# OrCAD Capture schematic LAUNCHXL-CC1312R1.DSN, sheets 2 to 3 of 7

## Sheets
2 5_EnergyTrace: size A3
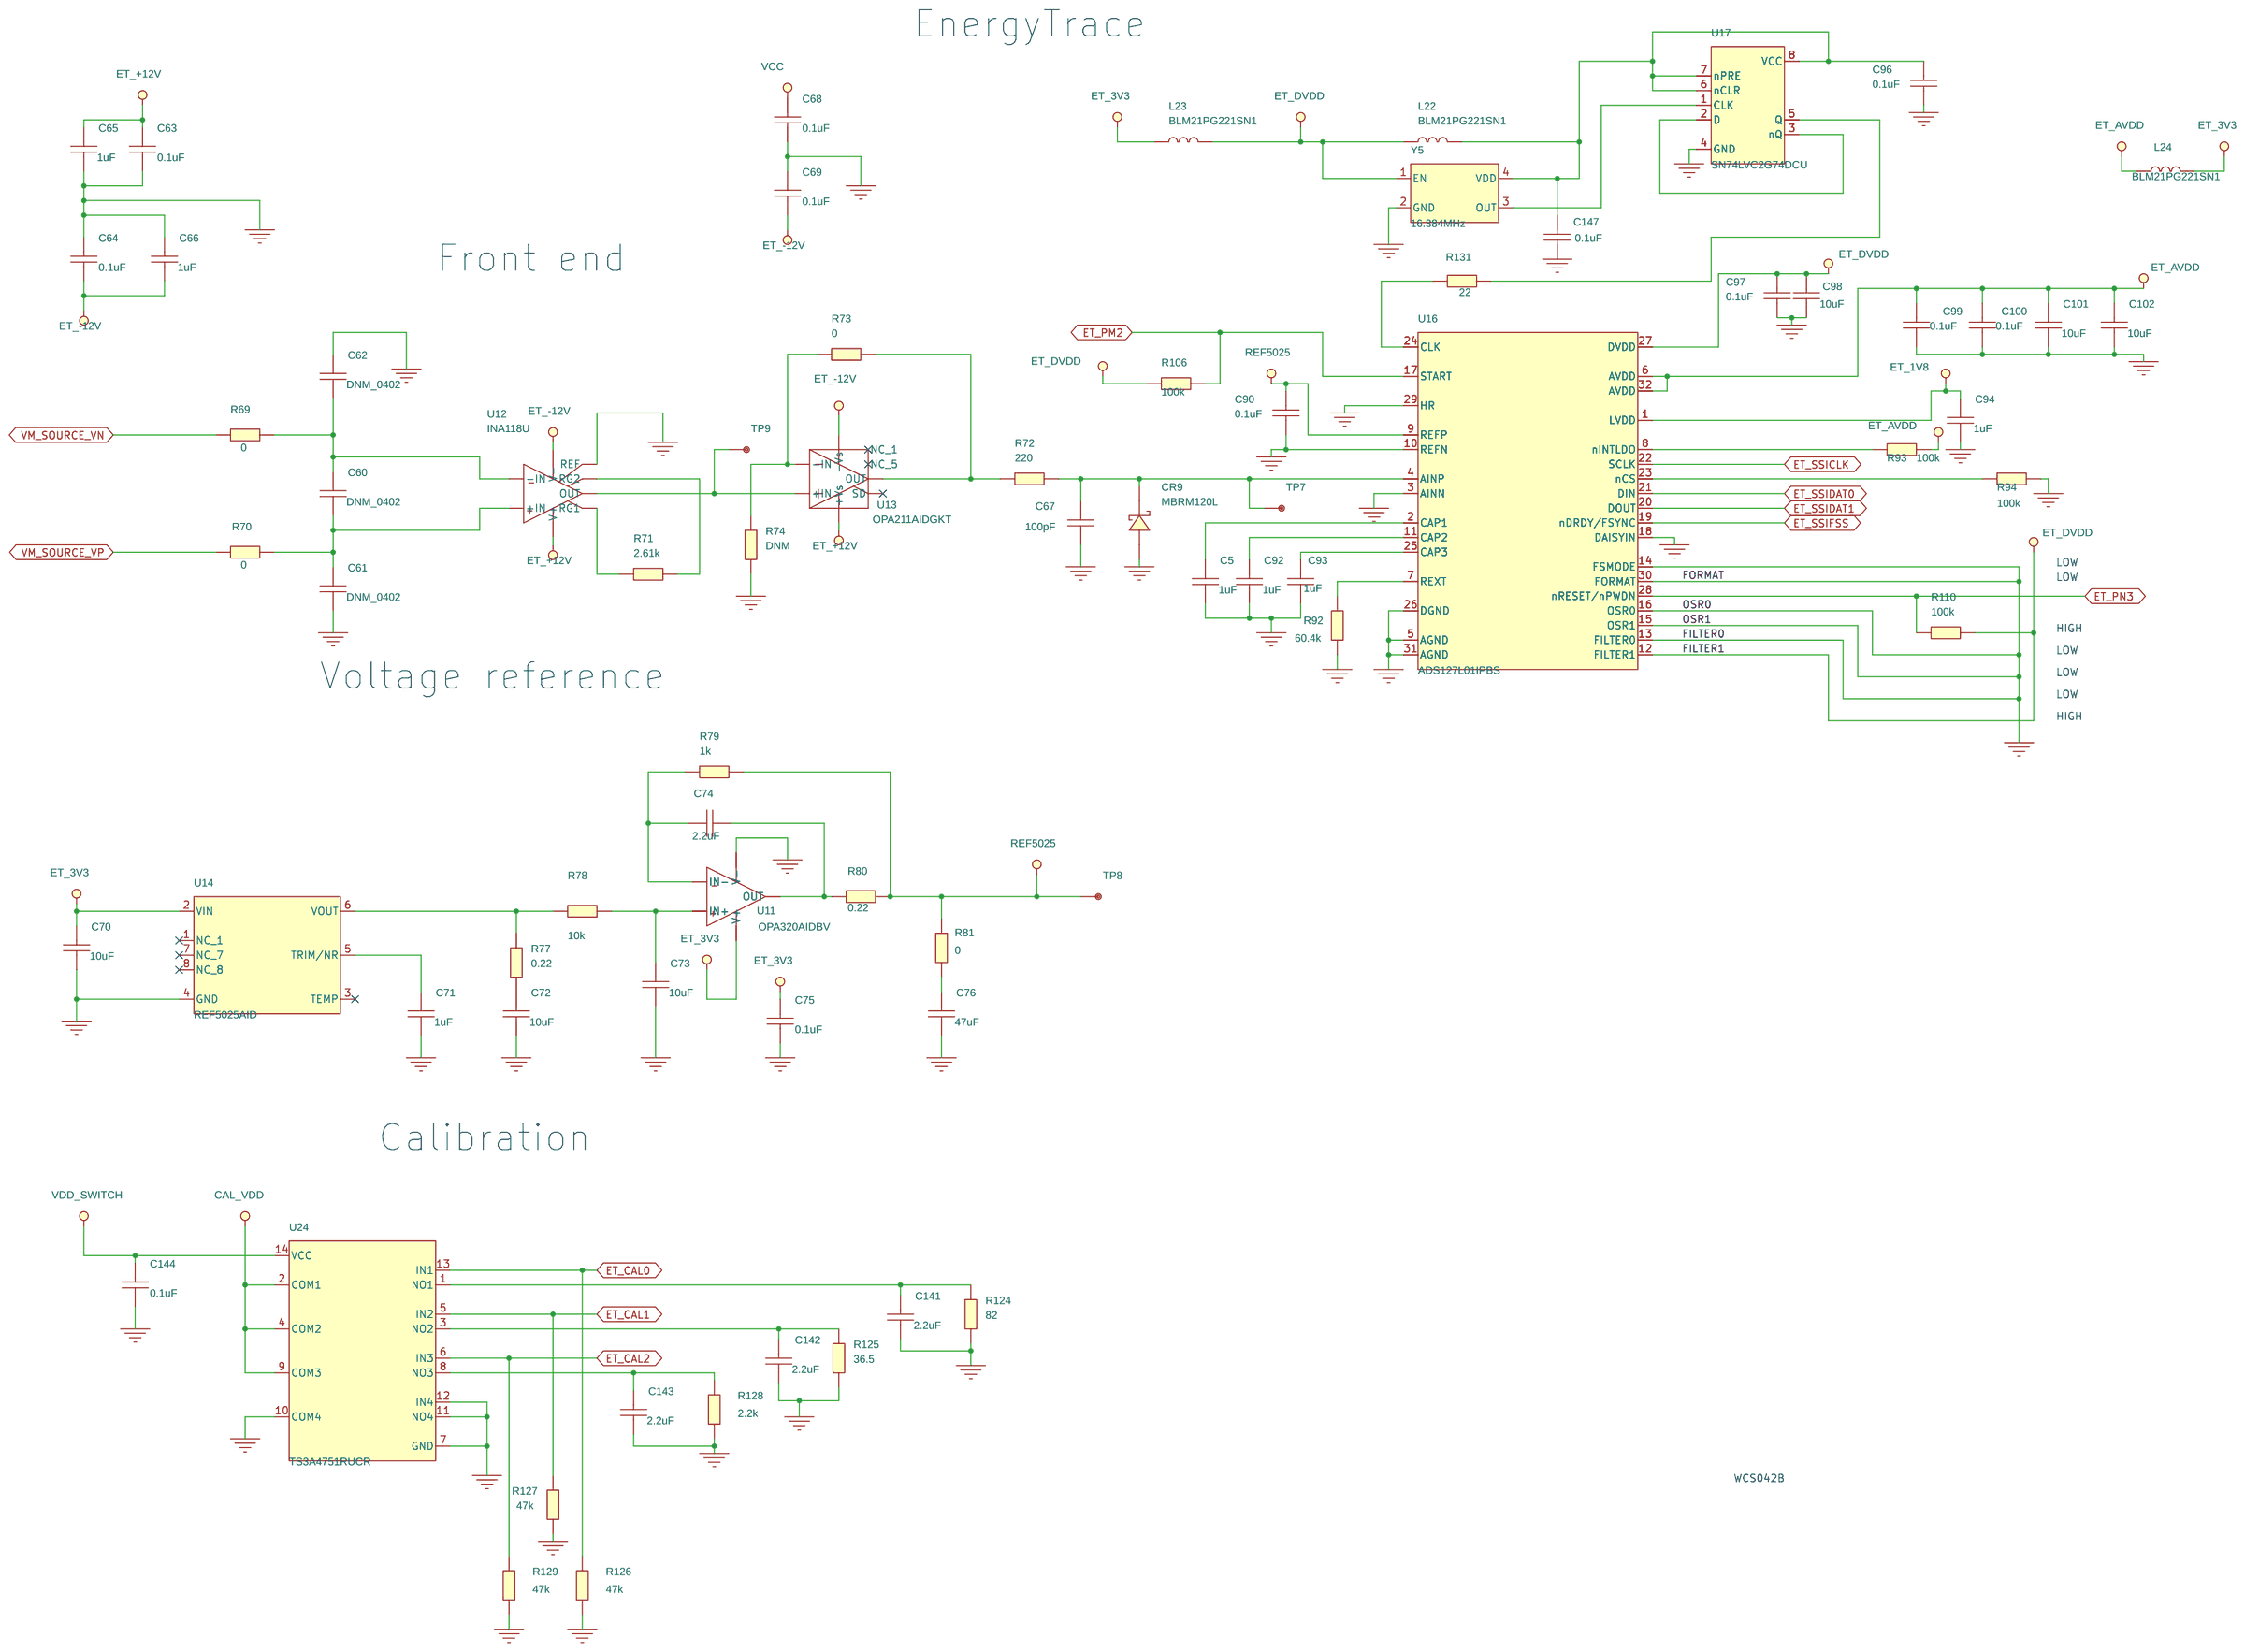
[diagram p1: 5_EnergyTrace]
3 7_Mech: size A3
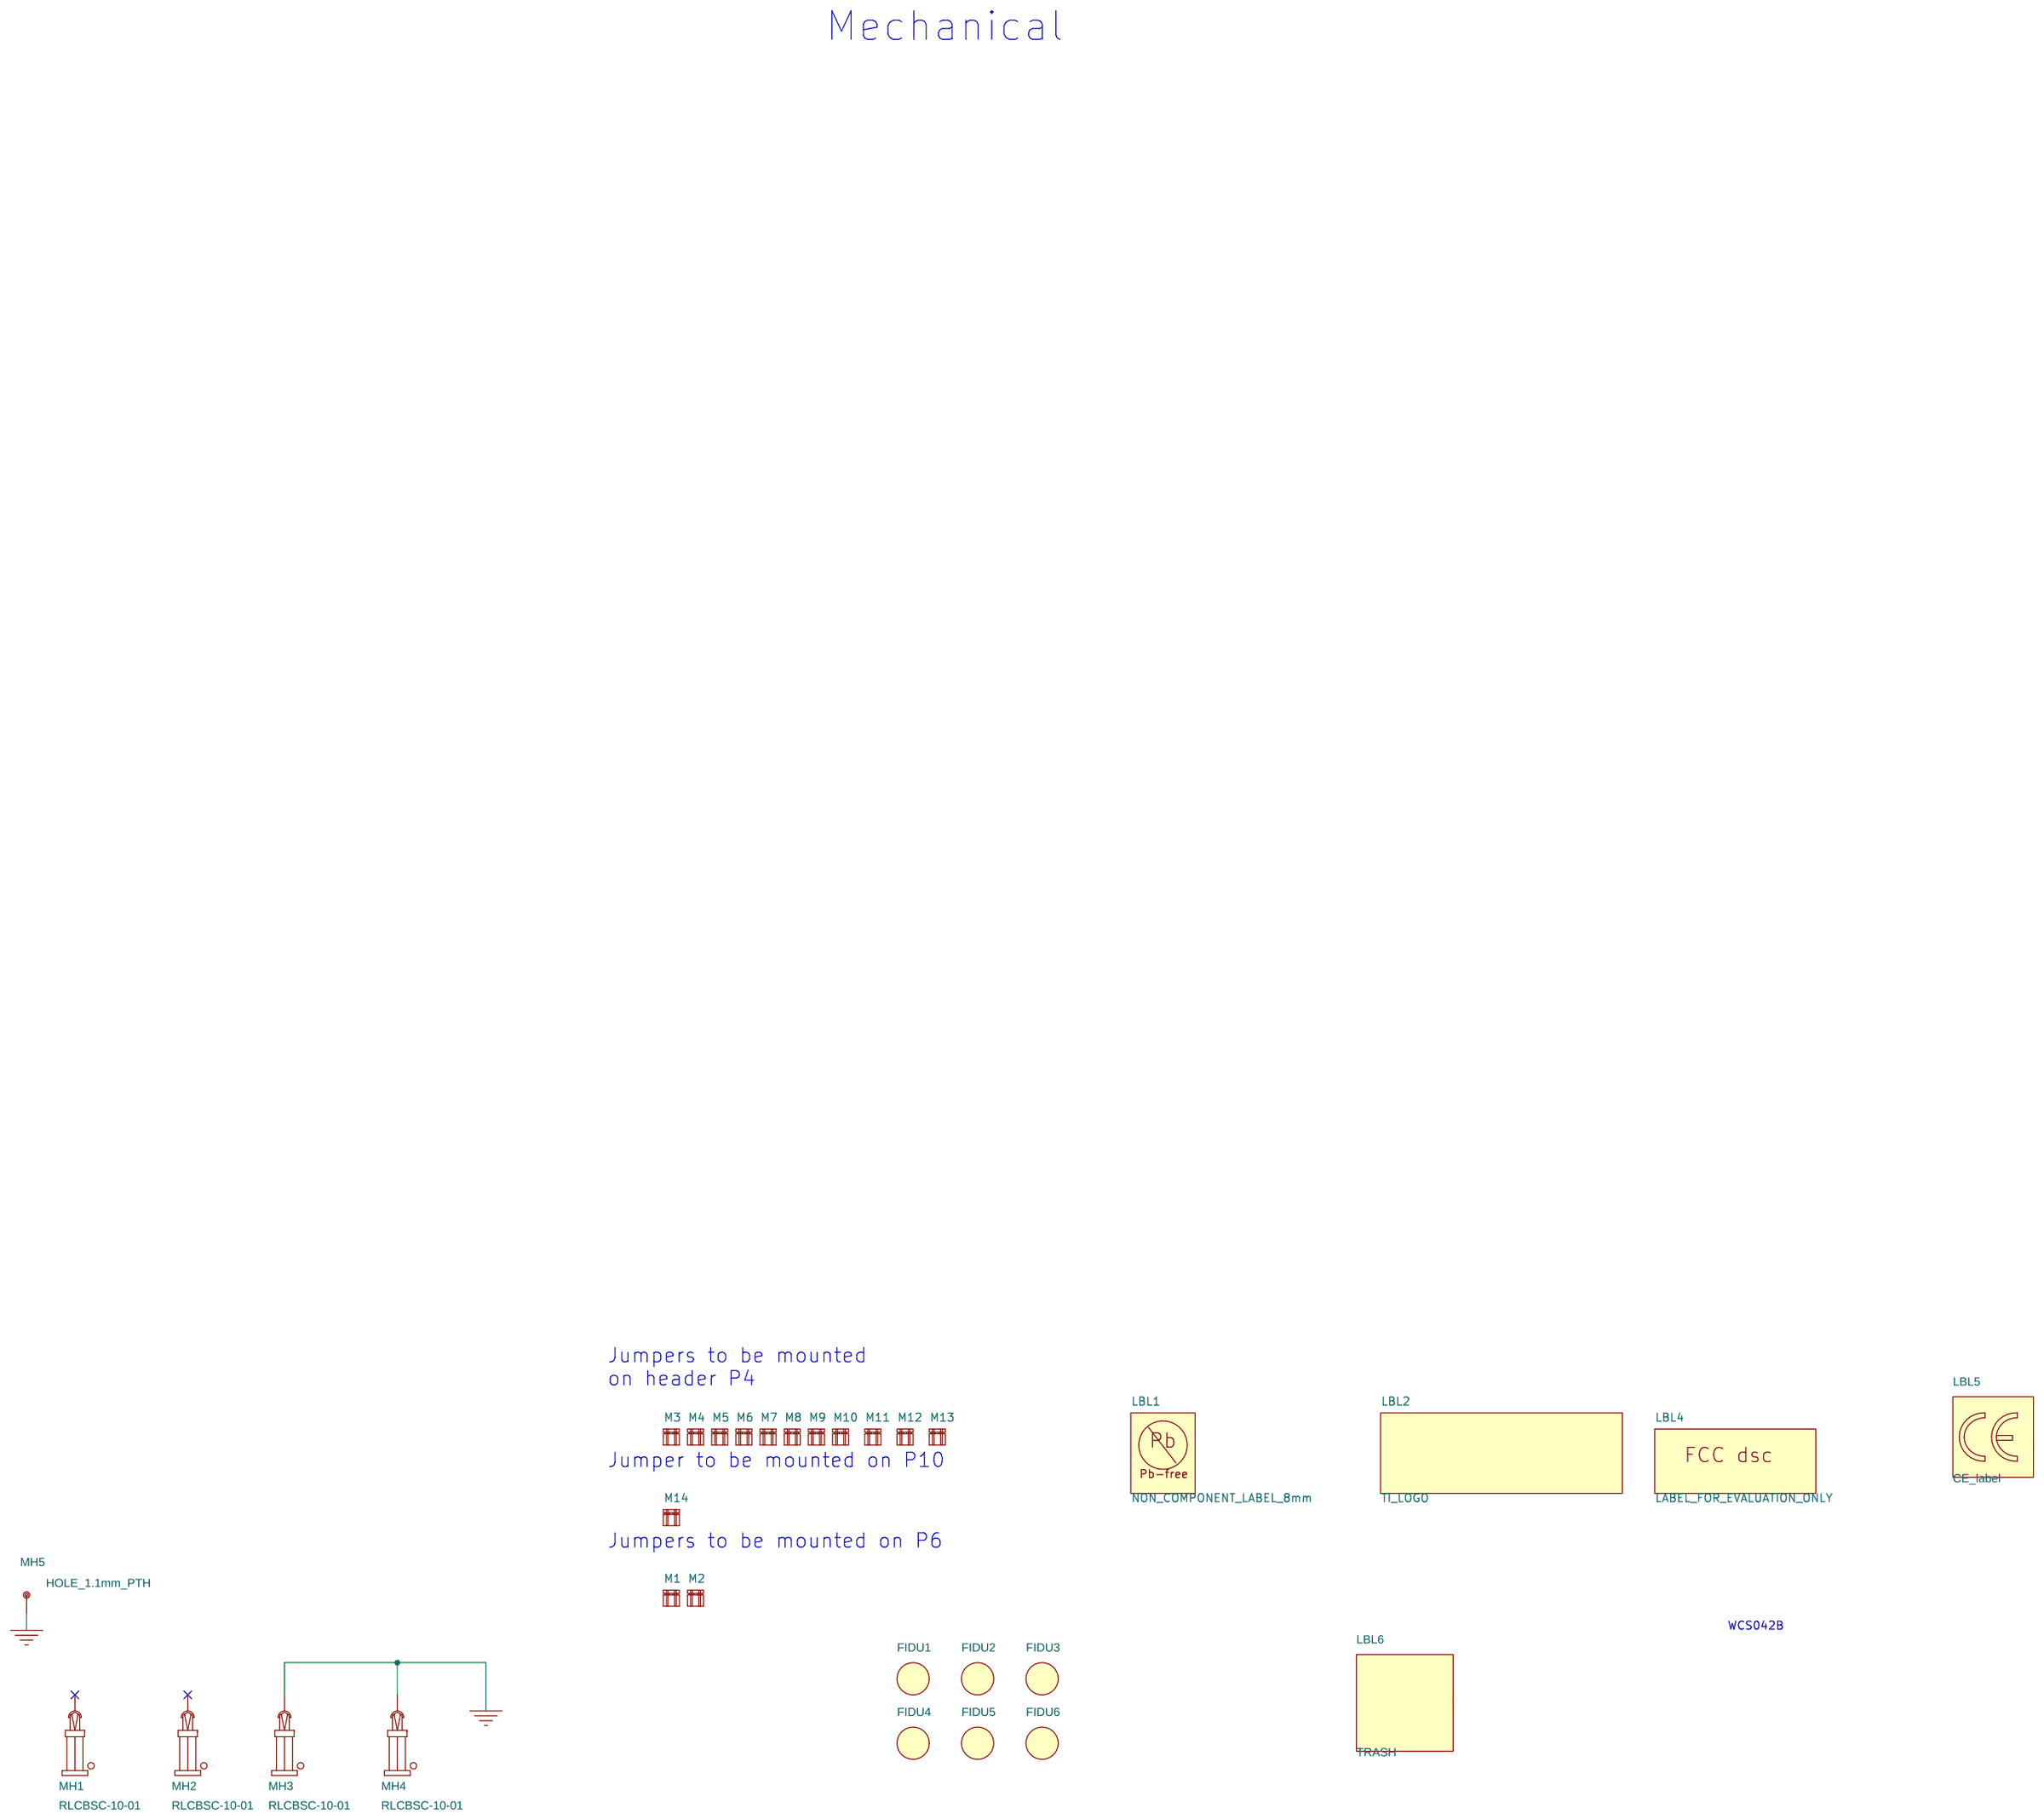
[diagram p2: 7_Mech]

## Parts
sheet 5_EnergyTrace
C5  1uF  [CAPC1005X60B2N]
C60  DNM_0402  [CAPC1005X60B2N]
C61  DNM_0402  [CAPC1005X60B2N]
C62  DNM_0402  [CAPC1005X60B2N]
C63  0.1uF  [CAPC1005X60B2N]
C64  0.1uF  [CAPC1005X60B2N]
C65  1uF  [CAPC1005X60B2N]
C66  1uF  [CAPC1005X60B2N]
C67  100pF  [CAPC1005X60B2N]
C68  0.1uF  [CAPC1005X60B2N]
C69  0.1uF  [CAPC1005X60B2N]
C70  10uF  [CAPC2012X150N]
C71  1uF  [CAPC1005X60B2N]
C72  10uF  [CAPC2012X150N]
C73  10uF  [CAPC2012X150N]
C74  2.2uF  [CAPC1005X60B2N]
C75  0.1uF  [CAPC1005X60B2N]
C76  47uF  [CAPC2012X150A2N]
C90  0.1uF  [CAPC1005X60B2N]
C92  1uF  [CAPC1005X60B2N]
C93  1uF  [CAPC1005X60B2N]
C94  1uF  [CAPC1005X60B2N]
C96  0.1uF  [CAPC1005X60B2N]
C97  0.1uF  [CAPC1005X60B2N]
C98  10uF  [CAPC2012X150N]
C99  0.1uF  [CAPC1005X60B2N]
C100  0.1uF  [CAPC1005X60B2N]
C101  10uF  [CAPC2012X150N]
C102  10uF  [CAPC2012X150N]
C141  2.2uF  [CAPC1005X60B2N]
C142  2.2uF  [CAPC1005X60B2N]
C143  2.2uF  [CAPC1005X60B2N]
C144  0.1uF  [CAPC1005X60B2N]
C147  0.1uF  [CAPC1005X60B2N]
CR9  MBRM120L  [DIO_MBRM120_A2N]
L22  BLM21PG221SN1  [INDC2012X150N]
L23  BLM21PG221SN1  [INDC2012X150N]
L24  BLM21PG221SN1  [INDC2012X150N]
R69  0  [RESC1005X40B2N]
R70  0  [RESC1005X40B2N]
R71  2.61k  [RESC1005X40N]
R72  220  [RESC1005X40B2N]
R73  0  [RESC1005X40B2N]
R74  DNM  [RESC1005X40B2N]
R77  0.22  [RESC1005X50A2N]
R78  10k  [RESC1005X40B2N]
R79  1k  [RESC1005X40A2N]
R80  0.22  [RESC1005X50A2N]
R81  0  [RESC1005X40B2N]
R92  60.4k  [RESC1005X40N]
R93  100k  [RESC1005X40B2N]
R94  100k  [RESC1005X40B2N]
R106  100k  [RESC1005X40B2N]
R110  100k  [RESC1005X40B2N]
R124  82  [RESC3216X75N]
R125  36.5  [RESC3225X75N]
R126  47k  [RESC1005X40N]
R127  47k  [RESC1005X40N]
R128  2.2k  [RESC1005X40A2N]
R129  47k  [RESC1005X40N]
R131  22  [RESC1005X40N]
TP7  HOLE_0.6mm_PTH  [MTG60_120]
TP8  HOLE_0.6mm_PTH  [MTG60_120]
TP9  HOLE_0.6mm_PTH  [MTG60_120]
U11  OPA320AIDBV  [SOT95P280X145-5A2N]
U12  INA118U  [SOIC127P600X175-8N]
U13  OPA211AIDGKT  [SOP65P490X110-8N]
U14  REF5025AID  [SOIC127P600X175-8A2N]
U16  ADS127L01IPBS  [QFP50P700X700X120-32A2N]
U17  SN74LVC2G74DCU  [SOP50P310X90-8N]
U24  TS3A4751RUCR  [QFNFC40P200X200X40-14A2N]
Y5  16.384MHz  [OSCSC508P500X700X180-4N]
sheet 7_Mech
FIDU1  FIDU_1.27mm  [FID127X142]
FIDU2  FIDU_1.27mm  [FID127X142]
FIDU3  FIDU_1.27mm  [FID127X142]
FIDU4  FIDU_1.27mm  [FID127X142]
FIDU5  FIDU_1.27mm  [FID127X142]
FIDU6  FIDU_1.27mm  [FID127X142]
LBL1  NON_COMPONENT_LABEL_8mm  [LABEL_PB-FREE_8MM_A2N]
LBL2  TI_LOGO  [TI_LOGO_1]
LBL4  LABEL_FOR_EVALUATION_ONLY  [LABEL_FOR_EVALUATION_ONLY]
LBL5  CE_label  [CE_label]
LBL6  TRASH  [TRASH]
M1  SNT-100-BK-G  [SAMTEC_SNT100BKG]
M2  SNT-100-BK-G  [SAMTEC_SNT100BKG]
M3  SNT-100-BK-G  [SAMTEC_SNT100BKG]
M4  SNT-100-BK-G  [SAMTEC_SNT100BKG]
M5  SNT-100-BK-G  [SAMTEC_SNT100BKG]
M6  SNT-100-BK-G  [SAMTEC_SNT100BKG]
M7  SNT-100-BK-G  [SAMTEC_SNT100BKG]
M8  SNT-100-BK-G  [SAMTEC_SNT100BKG]
M9  SNT-100-BK-G  [SAMTEC_SNT100BKG]
M10  SNT-100-BK-G  [SAMTEC_SNT100BKG]
M11  SNT-100-BK-G  [SAMTEC_SNT100BKG]
M12  SNT-100-BK-G  [SAMTEC_SNT100BKG]
M13  SNT-100-BK-G  [SAMTEC_SNT100BKG]
M14  SNT-100-BK-G  [SAMTEC_SNT100BKG]
MH1  RLCBSC-10-01  [MECH_RLCBSC1001_B2B]
MH2  RLCBSC-10-01  [MECH_RLCBSC1001_B2B]
MH3  RLCBSC-10-01  [MECH_RLCBSC1001_B2B]
MH4  RLCBSC-10-01  [MECH_RLCBSC1001_B2B]
MH5  HOLE_1.1mm_PTH  [MTG110_170]

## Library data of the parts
C5 C71 C92-C94 = CAPACITOR: CAPACITOR, CERAMIC X5R, 1uF, 16V, -10%/+10%, -55DEGC/+85DEGC, 0402, SMD; AutoDoc File: https://notefied-dynamic-precision.com/DB/Apps/Desktop/Item/Object.aspx?id=115295; BU Name: TEXAS INSTRUMENTS NORWAY; Client Status: UNDER_REVIEW; Datasheet URL 1: http://psearch.en.murata.com/capacitor/product/GRM155R61C105KA12%23.pdf; Datasheet URL 2: http://search.murata.co.jp/Ceramy/image/img/w_hinm/L0005E.pdf; Definied Quality: INDUSTRIAL; Dielectric Type: X5R; Esd Level: N/A; Last Time Buy: N/A; MPN: GRM155R61A105KE15D; MPN Status: ACTIVE; MSL: 1; MTBF: N/A; MTBF Standard: N/A; Manufacturer: MURATA; Max Oper Temp: +85DEGC; Max Tol: +10%; Min Oper Temp: -55DEGC; Min Tol: -10%; Mounting Type: SMD; NOTE Status: PREFERRED; Old Footprint: CAPC1005X60N,0402; PCB Package: 0402; Packing Size: 10000; Packing Type: TAPE_&_REEL; Part Number: 02-07863; Part Type: CAPACITOR\CERAMIC\0402\STANDARD; REACH/SVHC_COMPLIANCE: COMPLIANT; REACH/SVHC_DETAILS: SVHC LIST VERSION Jun 20, 2016; REACH/SVHC_SOURCE: REACH DECLARATION; REACH/SVHC_STATUS: UNAFFECTED; Revision: R002; RoHS Status: ROHS_COMPLIANT; Rtd Voltage: 16V; Vendor: MURATA; Vendor Part Number: GRM155R61C105KA12D; Vendor Part Status: ACTIVE; WEIGHT: 0.0016g
C60-C62 = CAPACITOR: CAPACITOR, CERAMIC, TBD, -55DEGC/+125DEGC, 0402, DNM, SMD; AutoDoc File: https://notefied-dynamic-precision.com/DB/Apps/Desktop/Item/Object.aspx?id=113344; BU Name: TEXAS INSTRUMENTS NORWAY; Budget Currency: USD; Budget Price: 0.00589; Country of Origin: MISSING INFO; Datasheet URL 1: N/A; Datasheet URL 2: N/A; Dielectric Type: MISSING-INFO; Last Time Buy: N/A; Lead Time: N/A; Max Oper Temp: +125DEGC; Min Oper Temp: -55DEGC; Mounting Type: SMD; PCB Package: 0402; Packing Size: 10000; Packing Type: TAPE_&_REEL; Part Number: 02-07616; Part Type: CAPACITOR\CERAMIC\0402\STANDARD; Revision: R000; RoHS Status: MISSING_INFO; Vendor: MANUFACTURER SELECTION; Vendor Part Number: CAPACITOR_0402_DNM_N/A_M; Vendor Part Status: ACTIVE; Weight: N/A
C63 C64 C68 C69 C75 C90 C96 C97 C99 C100 C144 C147 = CAPACITOR: CAPACITOR, CERAMIC X7R, 0.1uF, 25V, -10%/+10%, -55DEGC/+125DEGC, 0402, SMD; AutoDoc File: https://notefied-dynamic-precision.com/DB/Apps/Desktop/Item/Object.aspx?id=115293; BU Name: TEXAS INSTRUMENTS NORWAY; Client Status: UNDER_REVIEW; Datasheet URL 1: http://psearch.en.murata.com/capacitor/product/GRM155R71E104KE14%23.pdf; Datasheet URL 2: http://search.murata.co.jp/Ceramy/image/img/w_hinm/L0005E.pdf; Dielectric Type: X7R; Last Time Buy: N/A; LifeCycle Status: ACTIVE; MPN: GRM155R70J104KA01D; MPN Status: ACTIVE; Manufacturer: MURATA; Max Oper Temp: +125DEGC; Max Tol: +10%; Min Oper Temp: -55DEGC; Min Tol: -10%; Mounting Type: SMD; NOTE Status: PREFERRED; Old Footprint: CAPC1005X60N,0402; PCB Package: 0402; Packing Size: 10000; Packing Type: TAPE_&_REEL; Part Number: 02-07861; Part Type: CAPACITOR\CERAMIC\0402\STANDARD; REACH/SVHC_COMPLIANCE: COMPLIANT; REACH/SVHC_DETAILS: SVHC LIST VERSION Jun 20, 2016; REACH/SVHC_SOURCE: REACH DECLARATION; REACH/SVHC_STATUS: UNAFFECTED; Revision: R002; RoHS Status: ROHS_COMPLIANT; Rtd Voltage: 25V; Vendor: MURATA; Vendor Part Number: GRM155R71E104KE14D; Vendor Part Status: ACTIVE; WEIGHT: 0.0016g
C65 C66 = CAPACITOR: CAPACITOR, CERAMIC X5R, 1uF, 25V, -10%/+10%, -55DEGC/+85DEGC, 0402, SMD; AutoDoc File: https://notefied-dynamic-precision.com/DB/Apps/Desktop/Item/Object.aspx?id=115296; BU Name: TEXAS INSTRUMENTS NORWAY; Client Status: UNDER_REVIEW; Datasheet URL 1: http://psearch.en.murata.com/capacitor/product/GRM155R61E105KA12%23.pdf?graph=e32930247cd2da3b6fc5ccd8f3cf2bf2; Definied Quality: INDUSTRIAL; Dielectric Type: X5R; Esd Level: N/A; MPN: GRM155R61A105KE15D; MPN Status: ACTIVE; MSL: 1; MTBF: N/A; MTBF Standard: N/A; Manufacturer: MURATA; Max Oper Temp: +85DEGC; Max Tol: +10%; Min Oper Temp: -55DEGC; Min Tol: -10%; Mounting Type: SMD; NOTE Status: PREFERRED; Old Footprint: CAPC1005X60N,0402; PCB Package: 0402; Packing Size: 10000; Packing Type: TAPE_&_REEL; Part Number: 02-07864; Part Type: CAPACITOR\CERAMIC\0402\STANDARD; Revision: R001; RoHS Status: ROHS_COMPLIANT; Rtd Voltage: 25V; Vendor: MURATA; Vendor Part Number: GRM155R61E105KA12D; Vendor Part Status: ACTIVE; WEIGHT: 0.0016g
C67 = CAPACITOR: CAPACITOR, CERAMIC C0G/NP0, 100pF, 50V, -5%/+5%, -55DEGC/+125DEGC, 0402, SMD; AutoDoc File: https://notefied-dynamic-precision.com/DB/Apps/Desktop/Item/Object.aspx?id=113347; BU Name: TEXAS INSTRUMENTS NORWAY; Budget Currency: EUR; Budget Price: 0.004; Country of Origin: CHINA,PHILIPPINES; Datasheet URL 1: http://psearch.murata.com/capacitor/product/GRM1555C1H101JA01%23.pdf; Datasheet URL 2: http://search.murata.co.jp/Ceramy/image/img/w_hinm/L0005E.pdf; Dielectric Type: C0G/NP0; Last Time Buy: N/A; Lead Time: 12; Max Oper Temp: +125DEGC; Max Tol: +5%; Min Oper Temp: -55DEGC; Min Tol: -5%; Mounting Type: SMD; PCB Package: 0402; Packing Size: 10000; Packing Type: TAPE_&_REEL; Part Number: 02-07619; Part Type: CAPACITOR\CERAMIC\0402\STANDARD; REACH/SVHC_COMPLIANCE: COMPLIANT; REACH/SVHC_DETAILS: SVHC LIST VERSION Dec 17, 2015; REACH/SVHC_SOURCE: REACH DECLARATION; REACH/SVHC_STATUS: UNAFFECTED; Revision: R000; RoHS Status: ROHS_COMPLIANT; Rtd Voltage: 50V; Vendor: MURATA; Vendor Part Number: GRM1555C1H101JA01D; Vendor Part Status: ACTIVE; Weight: 0.0016g
C70 C72 C73 C98 C101 C102 = CAPACITOR: CAPACITOR, CERAMIC X7R, 10uF, 16V, -10%/+10%, -55DEGC/+125DEGC, 0805, SMD; ALT_SYMBOLS: CAPC2012X150L,CAPC2012X150M; AutoDoc File: https://notefied-dynamic-precision.com/DB/Apps/Desktop/Item/Object.aspx?id=94511; BU Name: DYNAMIC PRECISION GDANSK; Budget Currency: USD; Budget Price: 0.05; Client Status: UNDER_REVIEW; Country of Origin: SOUTH KOREA; Datasheet URL 1: http://www.samsungsem.com/kr/front/downloadcms.do?path=/kr/support/product-search/mlcc/__icsFiles/afieldfile/2015/10/15&fileName=S_CL21B106KOQNNNE.pdf; Datasheet URL 2: N/A; Dielectric Type: X7R; Last Time Buy: N/A; Lead Time: 11; Max Oper Temp: +125DEGC; Max Tol: +10%; Min Oper Temp: -55DEGC; Min Tol: -10%; Mounting Type: SMD; PCB Package: 0805; Packing Size: 2000; Packing Type: TAPE_&_REEL; Part Number: 02-05775; Part Type: CAPACITOR\CERAMIC\0805\STANDARD; Revision: R000; RoHS Status: ROHS_COMPLIANT; Rtd Voltage: 16V; Vendor: SAMSUNG ELECTRO-MECHANICS; Vendor Part Number: CL21B106KOQNNNE; Vendor Part Status: ACTIVE; Weight: 0.0166g
C74 C141-C143 = CAPACITOR: CAPACITOR, CERAMIC X5R, 2.2uF, 6.3V, -10%/+10%, -55DEGC/+85DEGC, 0402, SMD; AutoDoc File: https://notefied-dynamic-precision.com/DB/Apps/Desktop/Item/Object.aspx?id=113352; BU Name: TEXAS INSTRUMENTS NORWAY; Budget Currency: USD; Budget Price: 0.0126; Country of Origin: PHILIPPINES; Datasheet URL 1: http://psearch.murata.com/capacitor/product/GRM155R60J225KE95%23.pdf; Datasheet URL 2: http://psearch.en.murata.com/capacitor/product/GRM155R60J225KE95%23.html; Dielectric Type: X5R; Last Time Buy: N/A; Lead Time: N/A; Max Oper Temp: +85DEGC; Max Tol: +10%; Min Oper Temp: -55DEGC; Min Tol: -10%; Mounting Type: SMD; PCB Package: 0402; Packing Size: 10000; Packing Type: TAPE_&_REEL; Part Number: 02-07624; Part Type: CAPACITOR\CERAMIC\0402\STANDARD; Revision: R000; RoHS Status: ROHS_COMPLIANT; Rtd Voltage: 6.3V; Vendor: MURATA; Vendor Part Number: GRM155R60J225KE95D; Vendor Part Status: NRND; Weight: 0.0016g
C76 = CAPACITOR: CAPACITOR, CERAMIC X5R, 47uF, 10V, -20%/+20%, -55DEGC/+85DEGC, 0805, SMD; ALT_SYMBOLS: CAPC2012X150A2L,CAPC2012X150A2M; AutoDoc File: https://notefied-dynamic-precision.com/DB/Apps/Desktop/Item/Object.aspx?id=114133; BU Name: DYNAMIC PRECISION GDANSK; Client Status: UNDER_REVIEW; Datasheet URL 1: http://psearch.en.murata.com/capacitor/product/GRM21BR61A476ME15%23.pdf; Datasheet URL 2: N/A; Dielectric Type: X5R; Last Time Buy: N/A; Max Oper Temp: +85DEGC; Max Tol: +20%; Min Oper Temp: -55DEGC; Min Tol: -20%; Mounting Type: SMD; PCB Package: 0805; Packing Size: 3000; Packing Type: TAPE_&_REEL; Part Number: 02-07728; Part Type: CAPACITOR\CERAMIC\0805\STANDARD; Revision: R001; RoHS Status: ROHS_COMPLIANT; Rtd Voltage: 10V; Vendor: MURATA; Vendor Part Number: GRM21BR61A476ME15L; Vendor Part Status: ACTIVE; Weight: 0.023g
CR9 = DIODE_SCH_0: DIODE, SCHOTTKY POWER RECTIFIER, 20V, 1A, -55DEGC/+125DEGC, SMD; ALT_SYMBOLS: DIO_MBRM120_A2L,DIO_MBRM120_A2M; AutoDoc File: https://notefied-dynamic-precision.com/DB/Apps/Desktop/Item/Object.aspx?id=54665; BU Name: DYNAMIC PRECISION GDANSK; Budget Currency: USD; Budget Price: 0.12; Client Status: UNDER_REVIEW; Country of Origin: UNITED STATES; Datasheet URL 1: http://www.onsemi.com/pub/Collateral/MBRM120L-D.PDF; Datasheet URL 2: http://www.onsemi.com/pub/Collateral/457-04.PDF; Last Time Buy: N/A; Lead Time: 5; Max Oper Temp: +125DEGC; Min Oper Temp: -55DEGC; Mounting Type: SMD; Packing Size: 12000; Packing Type: TAPE_&_REEL; Part Number: 14-03151; Part Type: DIODE\SCHOTTKY; Revision: R002; RoHS Status: ROHS_COMPLIANT; Rtd Current: 1A; Rtd Voltage: 20V; Vendor: ON SEMICONDUCTOR; Vendor Part Number: MBRM120LT3G; Vendor Part Status: ACTIVE; Weight: 0.0163g
L22-L24 = INDUCTOR: FILTER, EMI, FERRITE BEAD, 220@100MHz, -25%/+25%, -55DEGC/+125DEGC, 0805, SMD; ALT_SYMBOLS: INDC2012X150L,INDC2012X150M; AutoDoc File: https://notefied-dynamic-precision.com/DB/Apps/Desktop/Item/Object.aspx?id=15278; BU Name: DYNAMIC PRECISION GDANSK; Budget Currency: EUR; Budget Price: 0.03; Client Status: UNDER_REVIEW; Country of Origin: JAPAN,SINGAPORE,THAILAND; Datasheet URL 1: http://search.murata.co.jp/Ceramy/image/img/PDF/ENG/L0110S0100BLM21P.pdf; Datasheet URL 2: http://search.murata.co.jp/Ceramy/image/img/w_hinm/L0110E.pdf; Frequency: 100MHz; Impedance: 220; Inductance: N/A; Last Time Buy: N/A; Lead Time: 9; Max Oper Temp: +125DEGC; Max Tol: +25%; Min Oper Temp: -55DEGC; Min Tol: -25%; Mounting Type: SMD; PCB Package: 0805; Packing Size: 4000; Packing Type: TAPE_&_REEL; Part Number: 04-00050; Part Type: FILTER\EMI\FERRITE_BEAD\0805; Resistance: 0.045; Revision: R002; RoHS Status: ROHS_COMPLIANT; Rtd Current: 2A; Rtd Voltage: N/A; Vendor: MURATA; Vendor Part Number: BLM21PG221SN1D; Vendor Part Status: ACTIVE; Weight: 0.0098g
R69 R70 R73 R81 = RESISTOR: RESISTOR, THICK FILM, 0, 0.063W, 50V, -55DEGC/+155DEGC, 0402, SMD; AutoDoc File: https://notefied-dynamic-precision.com/DB/Apps/Desktop/Item/Object.aspx?id=114568; BU Name: TEXAS INSTRUMENTS NORWAY; Budget Currency: EUR; Budget Price: 0.007; Client Status: UNDER_REVIEW; Country of Origin: ISRAEL; Datasheet URL 1: http://www.vishay.com/docs/20035/dcrcwe3.pdf; Datasheet URL 2: N/A; Last Time Buy: N/A; Lead Time: 14; Max Oper Temp: +155DEGC; Max TC: N/A; Max Tol: N/A; Min Oper Temp: -55DEGC; Min TC: N/A; Min Tol: N/A; Mounting Type: SMD; PCB Package: 0402; Packing Size: 10000; Packing Type: TAPE_&_REEL; Part Number: 01-22495; Part Type: RESISTOR\0402\JUMPER; REACH/SVHC_COMPLIANCE: COMPLIANT; REACH/SVHC_DETAILS: SVHC LIST VERSION Dec 17, 2015; REACH/SVHC_SOURCE: MATERIAL DECLARATION; REACH/SVHC_STATUS: UNAFFECTED; Resistor Type: THICK FILM; Revision: R000; RoHS Status: ROHS_COMPLIANT_WITH_EXEMPTION; Rtd Current: N/A; Rtd Power: 0.063W; Rtd Voltage: 50V; Vendor: VISHAY; Vendor Part Number: CRCW04020000Z0ED; Vendor Part Status: ACTIVE; Weight: 0.0006152g
R71 = RESISTOR: RESISTOR, THICK FILM, 2.61k, -1%/+1%, 0.063W, 50V, -55DEGC/+155DEGC, 0402, SMD; ALT_SYMBOLS: RESC1005X40L,RESC1005X40M; AutoDoc File: https://notefied-dynamic-precision.com/DB/Apps/Desktop/Item/Object.aspx?id=59349; BU Name: DYNAMIC PRECISION GDANSK; Budget Currency: EUR; Budget Price: 0.016; Country of Origin: ISRAEL; Datasheet URL 1: http://www.vishay.com/docs/20035/dcrcwe3.pdf; Datasheet URL 2: N/A; Last Time Buy: N/A; Lead Time: 18; Max Oper Temp: +155DEGC; Max TC: +100PPM/DEGC; Max Tol: +1%; Min Oper Temp: -55DEGC; Min TC: -100PPM/DEGC; Min Tol: -1%; Mounting Type: SMD; PCB Package: 0402; Packing Size: 10000; Packing Type: TAPE_&_REEL; Part Number: 01-04542; Part Type: RESISTOR\0402\PRECISION; Resistor Type: THICK FILM; Revision: R001; RoHS Status: ROHS_COMPLIANT; Rtd Current: N/A; Rtd Power: 0.063W; Rtd Voltage: 50V; Vendor: VISHAY; Vendor Part Number: CRCW04022K61FKED; Vendor Part Status: ACTIVE; Weight: 0.00065g
R72 = RESISTOR: RESISTOR, THICK FILM, 220, -5%/+5%, 0.063W, 50V, -55DEGC/+155DEGC, 0402, SMD; AutoDoc File: https://notefied-dynamic-precision.com/DB/Apps/Desktop/Item/Object.aspx?id=113319; BU Name: TEXAS INSTRUMENTS NORWAY; Budget Currency: EUR; Budget Price: 0.014; Client Status: UNDER_REVIEW; Country of Origin: ISRAEL; Datasheet URL 1: http://www.vishay.com/docs/20035/dcrcwe3.pdf; Datasheet URL 2: N/A; Last Time Buy: N/A; Lead Time: 18; Max Oper Temp: +155DEGC; Max TC: +200PPM/DEGC; Max Tol: +5%; Min Oper Temp: -55DEGC; Min TC: -200PPM/DEGC; Min Tol: -5%; Mounting Type: SMD; PCB Package: 0402; Packing Size: 10000; Packing Type: TAPE_&_REEL; Part Number: 01-22346; Part Type: RESISTOR\0402\STANDARD; REACH/SVHC_COMPLIANCE: COMPLIANT; REACH/SVHC_DETAILS: SVHC LIST VERSION Jun 20, 2016; REACH/SVHC_SOURCE: MATERIAL DECLARATION; REACH/SVHC_STATUS: UNAFFECTED; Resistor Type: THICK FILM; Revision: R001; RoHS Status: ROHS_COMPLIANT_WITH_EXEMPTION; Rtd Current: N/A; Rtd Power: 0.063W; Rtd Voltage: 50V; Vendor: VISHAY; Vendor Part Number: CRCW0402220RJNED; Vendor Part Status: ACTIVE; Weight: 0.00065g
R74 = RESISTOR: RESISTOR, DO NOT MOUNT, 0402, SMD; AutoDoc File: https://notefied-dynamic-precision.com/DB/Apps/Desktop/Item/Object.aspx?id=113312; BU Name: TEXAS INSTRUMENTS NORWAY; Budget Currency: N/A; Budget Price: N/A; Country of Origin: MISSING INFO; Datasheet URL 1: N/A; Datasheet URL 2: N/A; Last Time Buy: N/A; Lead Time: N/A; Max Oper Temp: N/A; Max TC: N/A; Max Tol: N/A; Min Oper Temp: N/A; Min TC: N/A; Min Tol: N/A; Mounting Type: SMD; PCB Package: 0402; Packing Size: N/A; Part Number: 01-22339; Part Type: RESISTOR\0402\STANDARD; Resistance: N/A; Resistor Type: THICK FILM; Revision: R000; RoHS Status: MISSING_INFO; Rtd Current: N/A; Rtd Power: N/A; Rtd Voltage: N/A; Vendor: DO NOT MOUNT; Vendor Part Status: ACTIVE; Weight: N/A
R77 R80 = RESISTOR: RESISTOR, THICK FILM, 0.22, -1%/+1%, 0.125W, -55DEGC/+155DEGC, 0402, SMD; ALT_SYMBOLS: RESC1005X50A2L,RESC1005X50A2M; AutoDoc File: https://notefied-dynamic-precision.com/DB/Apps/Desktop/Item/Object.aspx?id=97731; BU Name: DYNAMIC PRECISION GDANSK; Budget Currency: EUR; Budget Price: 0.291; Client Status: UNDER_REVIEW; Country of Origin: ISRAEL; Datasheet URL 1: http://www.vishay.com/docs/20019/rcwe.pdf; Datasheet URL 2: N/A; Last Time Buy: N/A; Lead Time: 10; Max Oper Temp: +155DEGC; Max TC: +100PPM/DEGC; Max Tol: +1%; Min Oper Temp: -55DEGC; Min TC: -100PPM/DEGC; Min Tol: -1%; Mounting Type: SMD; PCB Package: 0402; Packing Size: 10000; Packing Type: TAPE_&_REEL; Part Number: 01-20687; Part Type: RESISTOR\0402\LOW_RESISTANCE\PRECISION; Resistor Type: THICK FILM; Revision: R001; RoHS Status: ROHS_COMPLIANT_WITH_EXEMPTION; Rtd Current: N/A; Rtd Power: 0.125W; Rtd Voltage: N/A; Vendor: VISHAY; Vendor Part Number: RCWE0402R220FKEA; Vendor Part Status: ACTIVE; Weight: 0.0007g
R78 = RESISTOR: RESISTOR, THICK FILM, 10k, -5%/+5%, 0.063W, 50V, -55DEGC/+155DEGC, 0402, SMD; AutoDoc File: https://notefied-dynamic-precision.com/DB/Apps/Desktop/Item/Object.aspx?id=113326; BU Name: TEXAS INSTRUMENTS NORWAY; Budget Currency: EUR; Budget Price: 0.014; Client Status: UNDER_REVIEW; Country of Origin: ISRAEL; Datasheet URL 1: http://www.vishay.com/docs/20035/dcrcwe3.pdf; Datasheet URL 2: N/A; Definied Quality: INDUSTRIAL; Esd Level: N/A; Last Time Buy: N/A; Lead Time: 18; LifeCycle Status: ACTIVE; MPN: RESISTOR_0402_10k_+/-5%_50V_0.063W_M_+/-200ppm; MPN Status: ACTIVE; MSL: N/A; MTBF: N/A; MTBF Standard: N/A; Manufacturer: MANUFACTURER SELECTION; Max Oper Temp: +155DEGC; Max TC: +200PPM/DEGC; Max Tol: +5%; Min Oper Temp: -55DEGC; Min TC: -200PPM/DEGC; Min Tol: -5%; Mounting Type: SMD; NOTE Status: PREFERRED; Old Footprint: RESC1005X40N; PCB Package: 0402; Packing Size: 10000; Packing Type: TAPE_&_REEL; Part Number: 01-22353; Part Type: RESISTOR\0402\STANDARD; REACH/SVHC_COMPLIANCE: COMPLIANT; REACH/SVHC_DETAILS: SVHC LIST VERSION Jun 20, 2016; REACH/SVHC_SOURCE: MATERIAL DECLARATION; REACH/SVHC_STATUS: UNAFFECTED; Resistor Type: THICK FILM; Revision: R001; RoHS Status: ROHS_COMPLIANT_WITH_EXEMPTION; Rtd Current: N/A; Rtd Power: 0.063W; Rtd Voltage: 50V; Vendor: VISHAY; Vendor Part Number: CRCW040210K0JNED; Vendor Part Status: ACTIVE; WEIGHT: 0.00065g
R79 = RESISTOR: RESISTOR, THICK FILM, 1k, -1%/+1%, 0.063W, 50V, -55DEGC/+155DEGC, 0402, SMD; ALT_SYMBOLS: RESC1005X40A2L,RESC1005X40A2M; AutoDoc File: https://notefied-dynamic-precision.com/DB/Apps/Desktop/Item/Object.aspx?id=47959; BU Name: DYNAMIC PRECISION GDANSK; Budget Currency: EUR; Budget Price: 0.012; Client Status: UNDER_REVIEW; Country of Origin: ISRAEL; Datasheet URL 1: http://www.vishay.com/docs/20035/dcrcwe3.pdf; Datasheet URL 2: N/A; Last Time Buy: N/A; Lead Time: 14; Max Oper Temp: +155DEGC; Max TC: +100PPM/DEGC; Max Tol: +1%; Min Oper Temp: -55DEGC; Min TC: -100PPM/DEGC; Min Tol: -1%; Mounting Type: SMD; PCB Package: 0402; Packing Size: 10000; Packing Type: TAPE_&_REEL; Part Number: 01-02075; Part Type: RESISTOR\0402\PRECISION; Resistor Type: THICK FILM; Revision: R006; RoHS Status: ROHS_COMPLIANT_WITH_EXEMPTION; Rtd Current: N/A; Rtd Power: 0.063W; Rtd Voltage: 50V; Vendor: VISHAY; Vendor Part Number: CRCW04021K00FKED; Vendor Part Status: ACTIVE; Weight: 0.00060916g
R92 = RESISTOR: RESISTOR, THICK FILM, 60.4k, -1%/+1%, 0.063W, 50V, -55DEGC/+155DEGC, 0402, SMD; ALT_SYMBOLS: RESC1005X40L,RESC1005X40M; AutoDoc File: https://notefied-dynamic-precision.com/DB/Apps/Desktop/Item/Object.aspx?id=59465; BU Name: DYNAMIC PRECISION GDANSK; Budget Currency: EUR; Budget Price: 0.012; Client Status: UNDER_REVIEW; Country of Origin: ISRAEL; Datasheet URL 1: http://www.vishay.com/docs/20035/dcrcwe3.pdf; Datasheet URL 2: N/A; Last Time Buy: N/A; Lead Time: 14; Max Oper Temp: +155DEGC; Max TC: +100PPM/DEGC; Max Tol: +1%; Min Oper Temp: -55DEGC; Min TC: -100PPM/DEGC; Min Tol: -1%; Mounting Type: SMD; PCB Package: 0402; Packing Size: 10000; Packing Type: TAPE_&_REEL; Part Number: 01-04658; Part Type: RESISTOR\0402\PRECISION; Resistor Type: THICK FILM; Revision: R002; RoHS Status: ROHS_COMPLIANT_WITH_EXEMPTION; Rtd Current: N/A; Rtd Power: 0.063W; Rtd Voltage: 50V; Vendor: VISHAY; Vendor Part Number: CRCW040260K4FKED; Vendor Part Status: ACTIVE; Weight: 0.00060916g
R93 R94 R106 = RESISTOR: RESISTOR, THICK FILM, 100k, -5%/+5%, 0.063W, 50V, -55DEGC/+155DEGC, 0402, SMD; AutoDoc File: https://notefied-dynamic-precision.com/DB/Apps/Desktop/Item/Object.aspx?id=114565; BU Name: TEXAS INSTRUMENTS NORWAY; Budget Currency: EUR; Budget Price: 0.014; Client Status: UNDER_REVIEW; Country of Origin: UNITED STATES; Datasheet URL 1: http://www.vishay.com/docs/20035/dcrcwe3.pdf; Datasheet URL 2: N/A; Last Time Buy: N/A; Lead Time: 18; Max Oper Temp: +155DEGC; Max TC: +200PPM/DEGC; Max Tol: +5%; Min Oper Temp: -55DEGC; Min TC: -200PPM/DEGC; Min Tol: -5%; Mounting Type: SMD; PCB Package: 0402; Packing Size: 10000; Packing Type: TAPE_&_REEL; Part Number: 01-22492; Part Type: RESISTOR\0402\STANDARD; REACH/SVHC_COMPLIANCE: COMPLIANT; REACH/SVHC_DETAILS: SVHC LIST VERSION Jun 20, 2016; REACH/SVHC_SOURCE: MATERIAL DECLARATION; REACH/SVHC_STATUS: UNAFFECTED; Resistor Type: THICK FILM; Revision: R000; RoHS Status: ROHS_COMPLIANT; Rtd Current: N/A; Rtd Power: 0.063W; Rtd Voltage: 50V; Vendor: VISHAY; Vendor Part Number: CRCW0402100KJNED; Vendor Part Status: ACTIVE; Weight: 0.00065g
R110 = RESISTOR: RESISTOR, THICK FILM, 100k, -1%/+1%, 0.063W, 50V, -55DEGC/+155DEGC, 0402, SMD; ALT_SYMBOLS: RESC1005X40B2L,RESC1005X40B2M; AutoDoc File: https://notefied-dynamic-precision.com/DB/Apps/Desktop/Item/Object.aspx?id=115161; BU Name: TEXAS INSTRUMENTS NORWAY; Client Status: UNDER_REVIEW; Datasheet URL 1: http://www.ttelectronicsresistors.com/datasheets/WCR.pdf; Definied Quality: INDUSTRIAL; Esd Level: N/A; LifeCycle Status: ACTIVE; MPN: RESISTOR_0402_100k_+/-1%_50V_0.063W_M_+/-100PPM; MPN Status: ACTIVE; MSL: N/A; MTBF: N/A; MTBF Standard: N/A; Manufacturer: MANUFACTURER SELECTION; Max Oper Temp: +155DEGC; Max TC: +100PPM/DEGC; Max Tol: +1%; Min Oper Temp: -55DEGC; Min TC: -100PPM/DEGC; Min Tol: -1%; Mounting Type: SMD; NOTE Status: PREFERRED; Old Footprint: RESC1005X40N; PCB Package: 0402; Packing Size: 10000; Packing Type: TAPE_&_REEL; Part Number: 01-22536; Part Type: RESISTOR\0402\PRECISION; Resistor Type: THICK FILM; Revision: R001; RoHS Status: ROHS_COMPLIANT; Rtd Current: N/A; Rtd Power: 0.063W; Rtd Voltage: 50V; Vendor: TT ELECTRONICS; Vendor Part Number: WCR0402-100KFA; Vendor Part Status: ACTIVE
R124 = RESISTOR: RESISTOR, THICK FILM, 82, -1%/+1%, 0.25W, 200V, -55DEGC/+155DEGC, 1206, SMD; ALT_SYMBOLS: RESC3216X75L,RESC3216X75M; AutoDoc File: https://notefied-dynamic-precision.com/DB/Apps/Desktop/Item/Object.aspx?id=61724; BU Name: DYNAMIC PRECISION GDANSK; Budget Currency: EUR; Budget Price: 0.008; Client Status: UNDER_REVIEW; Country of Origin: ISRAEL; Datasheet URL 1: http://www.vishay.com/docs/20035/dcrcwe3.pdf; Datasheet URL 2: N/A; Last Time Buy: N/A; Lead Time: 12; Max Oper Temp: +155DEGC; Max TC: +100PPM/DEGC; Max Tol: +1%; Min Oper Temp: -55DEGC; Min TC: -100PPM/DEGC; Min Tol: -1%; Mounting Type: SMD; PCB Package: 1206; Packing Size: 5000; Packing Type: TAPE_&_REEL; Part Number: 01-06917; Part Type: RESISTOR\1206\PRECISION; Resistor Type: THICK FILM; Revision: R001; RoHS Status: ROHS_COMPLIANT_WITH_EXEMPTION; Rtd Current: N/A; Rtd Power: 0.25W; Rtd Voltage: 200V; Vendor: VISHAY; Vendor Part Number: CRCW120682R0FKEA; Vendor Part Status: ACTIVE; Weight: 0.010g
R125 = RESISTOR: RESISTOR, THICK FILM, 36.5, -1%/+1%, 0.5W, 200V, -55DEGC/+155DEGC, 1210, SMD; ALT_SYMBOLS: RESC3225X75L,RESC3225X75M; AutoDoc File: https://notefied-dynamic-precision.com/DB/Apps/Desktop/Item/Object.aspx?id=62122; BU Name: DYNAMIC PRECISION GDANSK; Budget Currency: USD; Budget Price: 0.0167; Country of Origin: MISSING INFO; Datasheet URL 1: http://www.vishay.com/docs/20035/dcrcwe3.pdf; Datasheet URL 2: N/A; Last Time Buy: N/A; Lead Time: 10; Max Oper Temp: +155DEGC; Max TC: +100PPM/DEGC; Max Tol: +1%; Min Oper Temp: -55DEGC; Min TC: -100PPM/DEGC; Min Tol: -1%; Mounting Type: SMD; PCB Package: 1210; Packing Size: 5000; Packing Type: TAPE_&_REEL; Part Number: 01-07315; Part Type: RESISTOR\1210\PRECISION; Resistor Type: THICK FILM; Revision: R001; RoHS Status: ROHS_COMPLIANT; Rtd Current: N/A; Rtd Power: 0.5W; Rtd Voltage: 200V; Vendor: VISHAY; Vendor Part Number: CRCW121036R5FKEA; Vendor Part Status: ACTIVE; Weight: 0.016g
R126 R127 R129 = RESISTOR: RESISTOR, THICK FILM, 47k, -5%/+5%, 0.063W, 50V, -55DEGC/+155DEGC, 0402, SMD; ALT_SYMBOLS: RESC1005X40L,RESC1005X40M; AutoDoc File: https://notefied-dynamic-precision.com/DB/Apps/Desktop/Item/Object.aspx?id=47144; BU Name: DYNAMIC PRECISION GDANSK; Budget Currency: EUR; Budget Price: 0.014; Country of Origin: MEXICO; Datasheet URL 1: http://www.vishay.com/docs/20035/dcrcwe3.pdf; Datasheet URL 2: N/A; Last Time Buy: N/A; Lead Time: 18; Max Oper Temp: +155DEGC; Max TC: +200PPM/DEGC; Max Tol: +5%; Min Oper Temp: -55DEGC; Min TC: -200PPM/DEGC; Min Tol: -5%; Mounting Type: SMD; PCB Package: 0402; Packing Size: 10000; Packing Type: TAPE_&_REEL; Part Number: 01-01260; Part Type: RESISTOR\0402\STANDARD; Resistor Type: THICK FILM; Revision: R001; RoHS Status: ROHS_COMPLIANT; Rtd Current: N/A; Rtd Power: 0.063W; Rtd Voltage: 50V; Vendor: VISHAY; Vendor Part Number: CRCW040247K0JNED; Vendor Part Status: ACTIVE; Weight: 0.00065g
R128 = RESISTOR: RESISTOR, THICK FILM, 2.2k, -1%/+1%, 0.063W, 50V, -55DEGC/+155DEGC, 0402, SMD; ALT_SYMBOLS: RESC1005X40A2L,RESC1005X40A2M; AutoDoc File: https://notefied-dynamic-precision.com/DB/Apps/Desktop/Item/Object.aspx?id=46123; BU Name: DYNAMIC PRECISION GDANSK; Budget Currency: EUR; Budget Price: 0.012; Client Status: UNDER_REVIEW; Country of Origin: ISRAEL; Datasheet URL 1: http://www.vishay.com/docs/20035/dcrcwe3.pdf; Datasheet URL 2: N/A; Last Time Buy: N/A; Lead Time: 14; Max Oper Temp: +155DEGC; Max TC: +100PPM/DEGC; Max Tol: +1%; Min Oper Temp: -55DEGC; Min TC: -100PPM/DEGC; Min Tol: -1%; Mounting Type: SMD; PCB Package: 0402; Packing Size: 10000; Packing Type: TAPE_&_REEL; Part Number: 01-00239; Part Type: RESISTOR\0402\PRECISION; Resistor Type: THICK FILM; Revision: R007; RoHS Status: ROHS_COMPLIANT_WITH_EXEMPTION; Rtd Current: N/A; Rtd Power: 0.063W; Rtd Voltage: 50V; Vendor: VISHAY; Vendor Part Number: CRCW04022K20FKED; Vendor Part Status: ACTIVE; Weight: 0.00060916g
R131 = RESISTOR: RESISTOR, THICK FILM, 22, -5%/+5%, 0.063W, 50V, -55DEGC/+155DEGC, 0402, SMD; ALT_SYMBOLS: RESC1005X40L,RESC1005X40M; AutoDoc File: https://notefied-dynamic-precision.com/DB/Apps/Desktop/Item/Object.aspx?id=47067; BU Name: DYNAMIC PRECISION GDANSK; Budget Currency: EUR; Budget Price: 0.014; Country of Origin: ISRAEL; Datasheet URL 1: http://www.vishay.com/docs/20035/dcrcwe3.pdf; Datasheet URL 2: N/A; Last Time Buy: N/A; Lead Time: 18; Max Oper Temp: +155DEGC; Max TC: +200PPM/DEGC; Max Tol: +5%; Min Oper Temp: -55DEGC; Min TC: -200PPM/DEGC; Min Tol: -5%; Mounting Type: SMD; PCB Package: 0402; Packing Size: 10000; Packing Type: TAPE_&_REEL; Part Number: 01-01183; Part Type: RESISTOR\0402\STANDARD; Resistor Type: THICK FILM; Revision: R001; RoHS Status: ROHS_COMPLIANT; Rtd Current: N/A; Rtd Power: 0.063W; Rtd Voltage: 50V; Vendor: VISHAY; Vendor Part Number: CRCW040222R0JNED; Vendor Part Status: ACTIVE; Weight: 0.00065g
TP7-TP9 = HOLE_PTH: NON COMPONENT, HOLE 0.6mm, PLATED HOLE; AutoDoc File: https://notefied-dynamic-precision.com/DB/Apps/Desktop/Item/Object.aspx?id=57336; BU Name: DYNAMIC PRECISION GDANSK; Part Number: 19-00057; Part Type: NON_COMPONENT\HOLE\PLATED; Revision: R001
U11 = IC_OPAMP_OPA320_SOT23-5: IC, ANALOG, RAIL-TO-RAIL I/O CMOS OPERATIONAL AMPLIFIER, -/+0.9V TO 5.5V, SOT23-5, SMD; ALT_SYMBOLS: SOT95P280X145-5A2L,SOT95P280X145-5A2M; AutoDoc File: https://notefied-dynamic-precision.com/DB/Apps/Desktop/Item/Object.aspx?id=113801; BU Name: DYNAMIC PRECISION GDANSK; Budget Currency: USD; Budget Price: 0.95; Client Status: UNDER_REVIEW; Country of Origin: THAILAND; Datasheet URL 1: http://www.ti.com/lit/ds/symlink/opa320.pdf; Datasheet URL 2: http://www.ti.com/lit/ml/mpds018l/mpds018l.pdf; Last Time Buy: N/A; Lead Time: 6; Max Oper Temp: +125DEGC; Min Oper Temp: -40DEGC; Mounting Type: SMD; PCB Package: SOT23-5; Packing Size: 250; Packing Type: TAPE_&_REEL; Part Number: 18-32984; Part Type: IC\ANALOG\AMPLIFIER; Revision: R003; RoHS Status: ROHS_COMPLIANT; Rtd Voltage: -/+0.9V TO 5.5V; Vendor: TEXAS INSTRUMENTS; Vendor Part Number: OPA320AIDBVT; Vendor Part Status: ACTIVE; Weight: 0.0203g
U12 = IC_OPAMP_INA118U_SO8: IC, ANALOG, INSTRUMENTATION AMPLIFIER, -/+15V, SO8, SMD; ALT_SYMBOLS: SOIC127P600X175-8L,SOIC127P600X175-8M; AutoDoc File: https://notefied-dynamic-precision.com/DB/Apps/Desktop/Item/Object.aspx?id=20164; BU Name: DYNAMIC PRECISION GDANSK; Budget Currency: USD; Budget Price: 5.80; Country of Origin: MALAYSIA; Datasheet URL 1: http://www.ti.com/lit/ds/symlink/ina118.pdf; Datasheet URL 2: http://www.ti.com/litv/pdf/msoi002j; Last Time Buy: N/A; Lead Time: 6; Max Oper Temp: +85DEGC; Min Oper Temp: -40DEGC; Mounting Type: SMD; PCB Package: SO8; Packing Size: 75; Packing Type: TUBE; Part Number: 18-01203; Part Type: IC\ANALOG\AMPLIFIER; Revision: R001; RoHS Status: ROHS_COMPLIANT; Rtd Voltage: -/+15V; Vendor: TEXAS INSTRUMENTS; Vendor Part Status: ACTIVE; Weight: 0.085g
U13 = IC_OPAMP_OPA211_MSOP8: IC, ANALOG, LOW NOISE PRECISION OPERATIONAL AMPLIFIER, 40V, MSOP8, SMD; ALT_SYMBOLS: SOP65P490X110-8L,SOP65P490X110-8M; AutoDoc File: https://notefied-dynamic-precision.com/DB/Apps/Desktop/Item/Object.aspx?id=65802; BU Name: DYNAMIC PRECISION GDANSK; Budget Currency: USD; Budget Price: 4.00; Country of Origin: GERMANY; Datasheet URL 1: http://www.ti.com/lit/ds/symlink/opa211.pdf; Datasheet URL 2: http://www.ti.com/litv/pdf/mpds028d; Last Time Buy: N/A; Lead Time: 6; Max Oper Temp: +150DEGC; Min Oper Temp: -55DEGC; Mounting Type: SMD; PCB Package: MSOP8; Packing Size: 250; Packing Type: TAPE_&_REEL; Part Number: 18-25892; Part Type: IC\ANALOG\AMPLIFIER; Revision: R000; RoHS Status: ROHS_COMPLIANT; Rtd Current: 0.03A; Rtd Voltage: 40V; Vendor: TEXAS INSTRUMENTS; Vendor Part Status: ACTIVE; Weight: 0.0248g
U14 = IC_REF_REF5025_SO8: IC, ANALOG, LOW-NOISE VERY LOW DRIFT PRECISION VOLTAGE REFERENCE, VIN: 2.7V TO 18V, VOUT:2.5V, 0.01A, SO8, SMD; ALT_SYMBOLS: SOIC127P600X175-8A2L,SOIC127P600X175-8A2M; AutoDoc File: https://notefied-dynamic-precision.com/DB/Apps/Desktop/Item/Object.aspx?id=115280; BU Name: DYNAMIC PRECISION GDANSK; Budget Currency: USD; Budget Price: 1.35; Client Status: UNDER_REVIEW; Datasheet URL 1: http://www.ti.com/lit/ds/symlink/ref5025.pdf; Max Oper Temp: +125DEGC; Min Oper Temp: -40DEGC; Mounting Type: SMD; PCB Package: SO8; Packing Size: 2500; Packing Type: TAPE_&_REEL; Part Number: 18-33432; Part Type: IC\ANALOG\PM\REFERENCE; Revision: R001; RoHS Status: ROHS_COMPLIANT; Rtd Current: 0.01A; Rtd Voltage: 2.5V; Vendor: TEXAS INSTRUMENTS; Vendor Part Number: REF5025AIDR; Vendor Part Status: ACTIVE
U16 = IC_ADC_ADS127L01_QFP32: IC, MIXED, 24-BIT WIDE-BANDWIDTH ANALOG TO DIGITAL CONVERTER, 2.7V TO 3.6V/1.7V TO 3.6V, TQFP32, SMD; ALT_SYMBOLS: QFP50P700X700X120-32A2L,QFP50P700X700X120-32A2M; AutoDoc File: https://notefied-dynamic-precision.com/DB/Apps/Desktop/Item/Object.aspx?id=115279; BU Name: DYNAMIC PRECISION GDANSK; Budget Currency: USD; Budget Price: 8.34; Client Status: UNDER_REVIEW; Datasheet URL 1: http://www.ti.com/lit/ds/symlink/ads127l01.pdf; Max Oper Temp: +125DEGC; Min Oper Temp: -40DEGC; Mounting Type: SMD; PCB Package: TQFP32; Packing Size: 250; Packing Type: TUBE; Part Number: 18-33431; Part Type: IC\MIXED\ADC; Revision: R001; RoHS Status: ROHS_COMPLIANT; Rtd Voltage: 2.7V TO 3.6V/1.7V TO 3.6V; Vendor: TEXAS INSTRUMENTS; Vendor Part Status: ACTIVE
U17 = IC_LOGIC_SN74LVC2G74_VSSOP8: IC, DIGITAL, LOGIC, D-TYPE FLIP-FLOP WITH CLEAR AND PRESET, 1.65V TO 5.5V, VSSOP8, SMD; ALT_SYMBOLS: SOP50P310X90-8L,SOP50P310X90-8M; AutoDoc File: https://notefied-dynamic-precision.com/DB/Apps/Desktop/Item/Object.aspx?id=83835; BU Name: DYNAMIC PRECISION GDANSK; Budget Currency: USD; Budget Price: 0.20; Client Status: UNDER_REVIEW; Country of Origin: THAILAND; Datasheet URL 1: http://www.ti.com/lit/ds/symlink/sn74lvc2g74.pdf; Datasheet URL 2: http://www.ti.com/litv/pdf/mpds050d; Last Time Buy: N/A; Lead Time: 6; Max Oper Temp: +85DEGC; Min Oper Temp: -40DEGC; Mounting Type: SMD; PCB Package: VSSOP8; Packing Size: 3000; Packing Type: TAPE_&_REEL; Part Number: 18-27150; Part Type: IC\DIGITAL\LOGIC\FLIP_FLOP; Revision: R001; RoHS Status: ROHS_COMPLIANT; Rtd Voltage: 1.65V TO 5.5V; Vendor: TEXAS INSTRUMENTS; Vendor Part Number: SN74LVC2G74DCUR; Vendor Part Status: ACTIVE; Weight: 0.011g
U24 = IC_SWITCH_TS3A4751_QFN14: IC, ANALOG, 0.9R LOW-VOLTAGE SINGLE-SUPPLY QUAD SPST ANALOG SWITCH, 1.6V TO 3.6V, QFN14, SMD; ALT_SYMBOLS: QFNFC40P200X200X40-14A2L,QFNFC40P200X200X40-14A2M; AutoDoc File: https://notefied-dynamic-precision.com/DB/Apps/Desktop/Item/Object.aspx?id=99155; BU Name: DYNAMIC PRECISION GDANSK; Budget Currency: USD; Budget Price: 0.42; Client Status: UNDER_REVIEW; Country of Origin: UNITED STATES; Datasheet URL 1: http://www.ti.com/lit/ds/symlink/ts3a4751.pdf; Datasheet URL 2: http://www.ti.com/litv/pdf/mpqf212b; Last Time Buy: N/A; Lead Time: 4; Max Oper Temp: +85DEGC; Min Oper Temp: -40DEGC; Mounting Type: SMD; PCB Package: QFN14; Packing Size: 3000; Packing Type: TAPE_&_REEL; Part Number: 18-30809; Part Type: IC\ANALOG\SWITCH; Revision: R001; RoHS Status: ROHS_COMPLIANT; Rtd Voltage: 1.6V TO 3.6V; Vendor: TEXAS INSTRUMENTS; Vendor Part Status: ACTIVE; Weight: 0.0038g
Y5 = XTAL_GEN_EN: CRYSTAL, OSCILLATOR, XO, 16.384MHz, -50PPM/+50PPM, 3.3V, -20DEGC/+70DEGC, SMD; ALT_SYMBOLS: OSCSC508P500X700X180-4L,OSCSC508P500X700X180-4M; AutoDoc File: https://notefied-dynamic-precision.com/DB/Apps/Desktop/Item/Object.aspx?id=92052; BU Name: DYNAMIC PRECISION GDANSK; Budget Currency: EUR; Budget Price: 0.77; Capacitance: 50pF; Client Status: UNDER_REVIEW; Country of Origin: CHINA; Datasheet URL 1: http://www.ctscorp.com/wp-content/uploads/2015/11/008-0256-0.pdf; Datasheet URL 2: http://www.ctscorp.com/connect_product_line/clock-oscillators/; Last Time Buy: N/A; Lead Time: 6; Max Oper Temp: +70DEGC; Max TC: +50PPM; Max Tol: N/A; Min Oper Temp: -20DEGC; Min TC: -50PPM; Min Tol: N/A; Mounting Type: SMD; Packing Size: 1000; Packing Type: TAPE_&_REEL; Part Number: 12-00625; Part Type: CRYSTAL\OSCILLATOR\XO; Revision: R000; RoHS Status: ROHS_COMPLIANT; Rtd Voltage: 3.3V; Vendor: CTS COMPONENTS; Vendor Part Number: CB3LV-3C-16M3840; Vendor Part Status: ACTIVE; Weight: 0.171497g
FIDU1-FIDU6 = FIDMARK: FIDUCIAL MARK, ROUND 1.27MM; Part Number: 19-00300; Part Type: NON_COMPONENT\FIDUCIAL
LBL1 = LABEL_Pb-free_V1: NON COMPONENT, LABEL, PB-FREE, 8mm; AutoDoc File: https://notefied-dynamic-precision.com/DB/Apps/Desktop/Item/Object.aspx?id=57438; BU Name: DYNAMIC PRECISION GDANSK; Part Number: 19-00159; Part Type: NON_COMPONENT\LABEL; Revision: R002
LBL2 = TI_LOGO_V1: NON COMPONENT, LABEL, TEXAS INSTRUMENTS LOGO; AutoDoc File: https://notefied-dynamic-precision.com/DB/Apps/Desktop/Item/Object.aspx?id=87770; BU Name: TEXAS INSTRUMENTS NORWAY; Part Number: 19-00350; Part Type: NON_COMPONENT\LABEL; Revision: R002
LBL4 = LABEL_FOR_EVALUATOIN_ONLY: NON COMPONENT, LABEL, FOR EVALUATION ONLY, NOT FCC APPROVED FOR RESALE; AutoDoc File: https://notefied-dynamic-precision.com/DB/Apps/Desktop/Item/Object.aspx?id=115268; BU Name: TEXAS INSTRUMENTS NORWAY; Part Number: 19-00830; Part Type: NON_COMPONENT\LABEL; Revision: R002
LBL5 = CE_LABEL: NON COMPONENT, LABEL, CE; Additional Datasheet URL: N/A; CLASS: DISCRETE; Country of Origin: Missing Info; Datasheet URL: http://www.ce-marking.com/CE-marking-logo.html; Mass: N/A; Mounting Type: Not Apply; NOTEfied URL: https://notefied-dynamic-precision.com/NOTEfiedWebInterface/part/show?partNumber=19-00351; Packing Size: N/A; Packing Type: Missing Info; Part Number: 19-00351; Part Type: Non Component|LABEL; ROHS: Missing Info; Revision: R005; Status: Released; Texas Part Status: Under Review; Type: Non Component; Vendor: NON_COMPONENT; Vendor Part Status: Active
LBL6 = TRASH_V1: NON COMPONENT, LABEL, TRASH; Additional Datasheet URL: N/A; CLASS: DISCRETE; Country of Origin: Missing Info; Datasheet URL: N/A; Mass: N/A; Mounting Type: Not Apply; NOTEfied URL: https://notefied-dynamic-precision.com/NOTEfiedWebInterface/part/show?partNumber=19-00362; Packing Size: N/A; Packing Type: Missing Info; Part Number: 19-00362; ROHS: Missing Info; Revision: R007; Status: Released; Texas Part Status: Under Review; Type: Non Component; Vendor: NON_COMPONENT; Vendor Part Status: Active
M1-M14 = MECH_SHUNT_JUMPER_V1: MECHANIC, SHUNT, CURRENT RATING 4.3A PER PIN, 2.54 X 5.08 X 6.1mm, BLACK; AutoDoc File: https://notefied-dynamic-precision.com/DB/Apps/Desktop/Item/Object.aspx?id=104092; BU Name: DYNAMIC PRECISION GDANSK; Budget Currency: USD; Budget Price: 0.146; Client Status: UNDER_REVIEW; Country of Origin: CHINA,COSTA RICA,MALAYSIA,SINGAPORE,UNITED STATES; Datasheet URL 1: http://suddendocs.samtec.com/catalog_english/snt.pdf; Datasheet URL 2: http://suddendocs.samtec.com/prints/snt-100-xx-x-x-mkt.pdf; Last Time Buy: N/A; Lead Time: 1; Max Oper Temp: +125DEGC; Min Oper Temp: -55DEGC; Mounting Type: NOT APPLY; Packing Size: 1; Packing Type: BULK; Part Number: 19-00498; Part Type: MECHANIC\SHUNT; REACH/SVHC_COMPLIANCE: COMPLIANT; REACH/SVHC_DETAILS: SVHC LIST VERSION Dec 17, 2015; REACH/SVHC_SOURCE: MATERIAL DECLARATION; REACH/SVHC_STATUS: UNAFFECTED; Revision: R002; RoHS Status: ROHS_COMPLIANT; Rtd Current: 4.3A; Vendor: SAMTEC; Vendor Part Status: ACTIVE; Weight: 0.11724g
MH1-MH4 = MECH_SUPPORT_SCREW_FASTENED_V1: MECHANIC, REVERSE LOCKING CIRCUIT BOARD SUPPORT, RLCBSC-10-01; AutoDoc File: https://notefied-dynamic-precision.com/DB/Apps/Desktop/Item/Object.aspx?id=116084; BU Name: DYNAMIC PRECISION GDANSK; Client Status: UNDER_REVIEW; Datasheet URL 1: http://www.essentracomponents.com.sg/images-line/pdfs/RLCBSC.pdf; Datasheet URL 2: N/A; Max Oper Temp: N/A; Min Oper Temp: N/A; Mounting Type: PTH; Packing Size: N/A; Packing Type: N/A; Part Number: 13-04327; Part Type: MECHANIC\OTHER; REACH/SVHC_COMPLIANCE: COMPLIANT; REACH/SVHC_DETAILS: SVHC LIST VERSION Dec 15, 2010; REACH/SVHC_SOURCE: REACH DECLARATION; REACH/SVHC_STATUS: UNAFFECTED; Revision: R003; RoHS Status: ROHS_COMPLIANT; Vendor: ESSENTRA; Vendor Part Status: ACTIVE
MH5 = HOLE_PTH: NON COMPONENT, HOLE 1.1mm, PLATED HOLE; AutoDoc File: http://notefied-dynamic-precision.com/DB/Apps/Desktop/Item/Object.aspx?id=57341; FPLIST: MTG110_170,; Part Number: 19-00062; Part Type: NON_COMPONENT\HOLE\PLATED; Revision: R001

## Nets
GND: C5.2 C61.2 C62.1 C63.2 C64.1 C65.2 C66.1 C67.2 C68.2 C69.1 C70.2 C71.2 C72.2 C73.2 C75.2 C76.2 C90.2 C92.2 C93.2 C94.2 C96.2 C97.2 C98.2 C99.2 C100.2 C101.2 C102.2 C141.2 C142.2 C143.2 C144.2 C147.2 CR9.2(ANODE) MH3.1 MH4.1 MH5.1 R74.1 R92.1 R94.1 R124.1 R125.1 R126.2 R127.2 R128.2 R129.2 U11.2(V-) U12.5(REF) U14.4(GND) U16.3(AINN) U16.5(AGND) U16.10(REFN) U16.13(FILTER0) U16.14(FSMODE) U16.15(OSR1) U16.16(OSR0) U16.18(DAISYIN) U16.26(DGND) U16.29(HR) U16.30(FORMAT) U16.31(AGND) U17.4(GND) U24.7(GND) U24.10(COM4) U24.11(NO4) U24.12(IN4) Y5.2(GND) ; also on sheet 1 4 5 6 7
VDD_SWITCH: C144.1 U24.14(VCC) ; also on sheet 1 4
CAL_VDD: U24.2(COM1) U24.4(COM2) U24.9(COM3) ; also on sheet 4
ET_1V8: C94.1 U16.1(LVDD) ; also on sheet 1
ET_3V3: C70.1 C75.1 L23.1 L24.2 U11.5(V+) U14.2(VIN) ; also on sheet 1
ET_+12V: C63.1 C65.1 C68.1 U12.7(V+) U13.7(+Vs) ; also on sheet 1
ET_-12V: C64.2 C66.2 C69.2 U12.4(V-) U13.4(-Vs) ; also on sheet 1
ET_AVDD: C99.1 C100.1 C101.1 C102.1 L24.1 R93.1 U16.6(AVDD) U16.32(AVDD)
ET_CAL0: R126.1 U24.13(IN1) ; also on sheet 5
ET_CAL1: R127.1 U24.5(IN2) ; also on sheet 5
ET_CAL2: R129.1 U24.6(IN3) ; also on sheet 5
ET_DVDD: C97.1 C98.1 L22.1 L23.2 R106.2 R110.1 U16.12(FILTER1) U16.27(DVDD) Y5.1(EN)
ET_PM2: R106.1 U16.17(START) ; also on sheet 5
ET_PN3: R110.2 U16.28(nRESET/nPWDN) ; also on sheet 5
ET_SSICLK: U16.22(SCLK) ; also on sheet 5
ET_SSIDAT0: U16.21(DIN) ; also on sheet 5
ET_SSIDAT1: U16.20(DOUT) ; also on sheet 5
ET_SSIFSS: U16.19(nDRDY/FSYNC) ; also on sheet 5
REF5025: C90.1 R79.1 R80.1 R81.1 TP8.1 U16.9(REFP)
VM_SOURCE_VN: R69.2 ; also on sheet 4
VM_SOURCE_VP: R70.2 ; also on sheet 4
N1532633: C60.1 C62.2 R69.1 U12.2(-IN)
N1532640: C60.2 C61.1 R70.1 U12.3(+IN)
N1532863: R71.2 U12.1(RG1)
N1532870: R71.1 U12.8(RG2)
N1536103: C67.1 CR9.1(CATHODE) R72.1 TP7.1 U16.4(AINP)
N1536178: TP9.1 U12.6(OUT) U13.3(+IN)
N1536208: R73.2 R74.2 U13.2(-IN)
N1536226: R72.2 R73.1 U13.6(OUT)
N1540868: C71.1 U14.5(TRIM/NR)
N1541303: R77.2 R78.2 U14.6(VOUT)
N1541344: C73.1 R78.1 U11.3(IN+)
N1541677: C74.1 R79.2 U11.4(IN-)
N1541715: C74.2 R80.2 U11.1(OUT)
N1542217: C76.1 R81.2
N1589081: C5.1 U16.2(CAP1)
N1589096: C92.1 U16.11(CAP2)
N1589103: C93.1 U16.25(CAP3)
N1594429: C96.1 C147.1 L22.2 U17.6(nCLR) U17.7(nPRE) U17.8(VCC) Y5.4(VDD)
N1594693: U17.1(CLK) Y5.3(OUT)
N1594702: R131.2 U16.24(CLK)
N1594966: U17.2(D) U17.3(nQ)
N1594995: R131.1 U17.5(Q)
N1595900: R92.2 U16.7(REXT)
N1605224: R93.2 U16.8(nINTLDO)
N1605907: R94.2 U16.23(nCS)
N1699637: C141.1 R124.2 U24.1(NO1)
N1715528: C142.1 R125.2 U24.3(NO2)
N1716003: C143.1 R128.1 U24.8(NO3)
N2367219: C72.1 R77.1

Not connected (* = marked no-connect by the designer): FIDU1 1; FIDU2 1; FIDU3 1; FIDU4 1; FIDU5 1; FIDU6 1; LBL5 1; LBL6 1(NC); MH1 1*; MH2 1*; U13 1(NC)* 5(NC)* 8(SD)*; U14 1(NC)* 3(TEMP)* 7(NC)* 8(NC)*

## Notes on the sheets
sheet 2
- EnergyTrace
- Front end
- LOW
- LOW
- HIGH
- LOW
- Voltage reference
- LOW
- LOW
- HIGH
- Calibration
- WCS042B
sheet 3
- Mechanical
- Jumpers to be mounted
  on header P4
- Jumper to be mounted on P10
- Jumpers to be mounted on P6
- WCS042B
